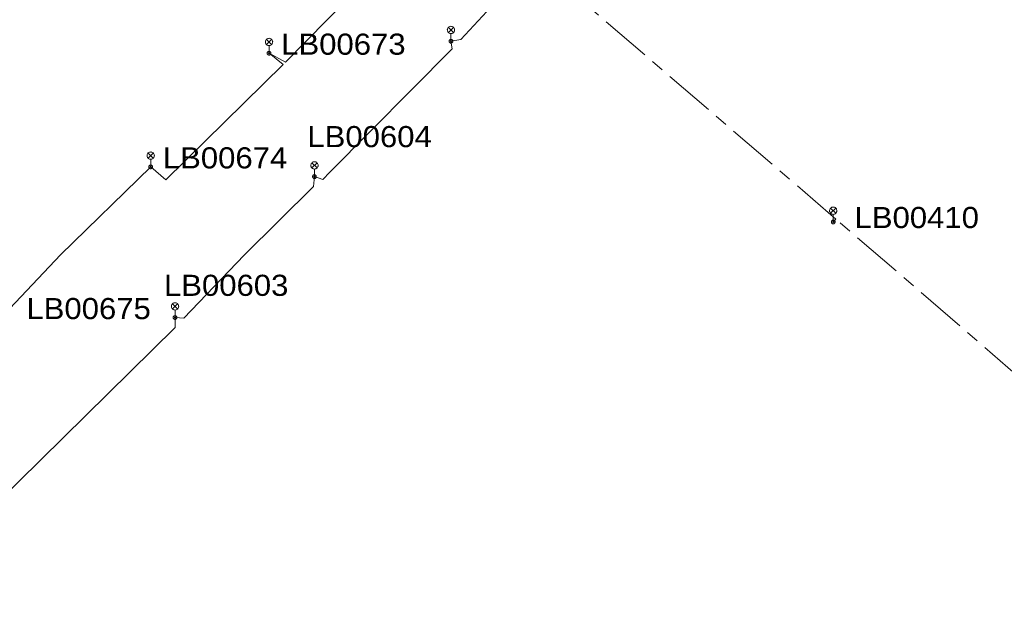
# Model space of a CAD drawing. Extents: x -688049 to -687261, y -973611 to -973038.
# Drawn here: x -687451.2 to -687350.2, y -973532.3 to -973470.9 of the extents above; entities that cross this region are included whole.
import ezdxf

# ---------------------------------------------------------------- set-up
doc = ezdxf.new("R2010")
doc.units = 0
doc.header["$LTSCALE"] = 0.87
doc.linetypes.add('LONG_DASH_SHORT_DASH', pattern=[9.9, 6, -1.2, 1.5, -1.2])
doc.layers.add('1', color=7, linetype='Continuous', lineweight=13)

msp = doc.modelspace()

# ---------------------------------------------------------------- linework, layer by layer
at = {"layer": '1', "linetype": 'LONG_DASH_SHORT_DASH'}
for p, q in [((-687367.46, -973491.32), (-687394.43, -973468.17)), ((-687367.46, -973491.32), (-687367.74, -973491.62)), ((-687341.72, -973513.53), (-687367.46, -973491.32))]:
    msp.add_line(p, q, dxfattribs=at)
at = {"layer": '1'}
for p, q in [((-687407.215, -973471.665), (-687406.685, -973472.195)), ((-687407.215, -973472.195), (-687406.685, -973471.665)), ((-687425.875, -973472.895), (-687425.345, -973473.425)), ((-687425.875, -973473.425), (-687425.345, -973472.895)), ((-687406.95, -973473.08), (-687406.95, -973472.305)), ((-687425.61, -973474.31), (-687425.61, -973473.535)), ((-687438.015, -973484.555), (-687437.485, -973485.085)), ((-687438.015, -973485.085), (-687437.485, -973484.555)), ((-687437.75, -973485.97), (-687437.75, -973485.195)), ((-687421.215, -973485.555), (-687420.685, -973486.085)), ((-687421.215, -973486.085), (-687420.685, -973485.555)), ((-687420.95, -973486.97), (-687420.95, -973486.195)), ((-687368.005, -973490.205), (-687367.475, -973490.735)), ((-687368.005, -973490.735), (-687367.475, -973490.205)), ((-687367.74, -973491.62), (-687367.74, -973490.845)), ((-687435.515, -973500.015), (-687434.985, -973500.545)), ((-687435.515, -973500.545), (-687434.985, -973500.015)), ((-687435.25, -973501.43), (-687435.25, -973500.655))]:
    msp.add_line(p, q, dxfattribs=at)
for points in [[(-687405.56, -973454.77), (-687404.641, -973456.423), (-687407.326, -973458.82), (-687411.049, -973462.143), (-687423.916, -973475.233), (-687425.61, -973474.31)], [(-687406.95, -973473.08), (-687405.926, -973472.922), (-687401.497, -973468.097), (-687399.617, -973467.227), (-687396.262, -973466.483), (-687385.16, -973458.6), (-687385.16, -973457.575), (-687384.133, -973456.25)], [(-687406.95, -973473.08), (-687406.828, -973473.853), (-687419.37, -973486.514), (-687420.101, -973487.253), (-687420.95, -973486.97)], [(-687425.61, -973474.31), (-687424.155, -973475.479), (-687436.21, -973487.29), (-687437.75, -973485.97), (-687447.006, -973494.997), (-687452.208, -973500.487), (-687452.51, -973500.51)], [(-687420.95, -973486.97), (-687421.047, -973487.985), (-687428.168, -973495.036), (-687434.342, -973501.48), (-687435.25, -973501.43)], [(-687435.25, -973501.43), (-687435.25, -973502.448), (-687465.092, -973531.834), (-687465.97, -973532.28)]]:
    msp.add_lwpolyline(points, dxfattribs=at)
for points in [[(-687406.575, -973471.93), (-687406.581, -973471.865), (-687406.598, -973471.802), (-687406.625, -973471.742), (-687406.663, -973471.689), (-687406.709, -973471.643), (-687406.763, -973471.605), (-687406.822, -973471.578), (-687406.885, -973471.561), (-687406.95, -973471.555), (-687407.015, -973471.561), (-687407.078, -973471.578), (-687407.138, -973471.605), (-687407.191, -973471.643), (-687407.237, -973471.689), (-687407.275, -973471.742), (-687407.302, -973471.802), (-687407.319, -973471.865), (-687407.325, -973471.93), (-687407.319, -973471.995), (-687407.302, -973472.058), (-687407.275, -973472.117), (-687407.237, -973472.171), (-687407.191, -973472.217), (-687407.138, -973472.255), (-687407.078, -973472.282), (-687407.015, -973472.299), (-687406.95, -973472.305), (-687406.885, -973472.299), (-687406.822, -973472.282), (-687406.763, -973472.255), (-687406.709, -973472.217), (-687406.663, -973472.171), (-687406.625, -973472.117), (-687406.598, -973472.058), (-687406.581, -973471.995)], [(-687425.235, -973473.16), (-687425.241, -973473.095), (-687425.258, -973473.032), (-687425.285, -973472.972), (-687425.323, -973472.919), (-687425.369, -973472.873), (-687425.422, -973472.835), (-687425.482, -973472.808), (-687425.545, -973472.791), (-687425.61, -973472.785), (-687425.675, -973472.791), (-687425.738, -973472.808), (-687425.798, -973472.835), (-687425.851, -973472.873), (-687425.897, -973472.919), (-687425.935, -973472.972), (-687425.962, -973473.032), (-687425.979, -973473.095), (-687425.985, -973473.16), (-687425.979, -973473.225), (-687425.962, -973473.288), (-687425.935, -973473.348), (-687425.897, -973473.401), (-687425.851, -973473.447), (-687425.798, -973473.485), (-687425.738, -973473.512), (-687425.675, -973473.529), (-687425.61, -973473.535), (-687425.545, -973473.529), (-687425.482, -973473.512), (-687425.422, -973473.485), (-687425.369, -973473.447), (-687425.323, -973473.401), (-687425.285, -973473.348), (-687425.258, -973473.288), (-687425.241, -973473.225)], [(-687406.76, -973473.08), (-687406.763, -973473.047), (-687406.771, -973473.015), (-687406.785, -973472.985), (-687406.804, -973472.958), (-687406.828, -973472.934), (-687406.855, -973472.915), (-687406.885, -973472.901), (-687406.917, -973472.893), (-687406.95, -973472.89), (-687406.983, -973472.893), (-687407.015, -973472.901), (-687407.045, -973472.915), (-687407.072, -973472.934), (-687407.096, -973472.958), (-687407.115, -973472.985), (-687407.129, -973473.015), (-687407.137, -973473.047), (-687407.14, -973473.08), (-687407.137, -973473.113), (-687407.129, -973473.145), (-687407.115, -973473.175), (-687407.096, -973473.202), (-687407.072, -973473.226), (-687407.045, -973473.245), (-687407.015, -973473.259), (-687406.983, -973473.267), (-687406.95, -973473.27), (-687406.917, -973473.267), (-687406.885, -973473.259), (-687406.855, -973473.245), (-687406.828, -973473.226), (-687406.804, -973473.202), (-687406.785, -973473.175), (-687406.771, -973473.145), (-687406.763, -973473.113)], [(-687406.9, -973473.08), (-687406.901, -973473.071), (-687406.903, -973473.063), (-687406.907, -973473.055), (-687406.912, -973473.048), (-687406.918, -973473.042), (-687406.925, -973473.037), (-687406.933, -973473.033), (-687406.941, -973473.031), (-687406.95, -973473.03), (-687406.959, -973473.031), (-687406.967, -973473.033), (-687406.975, -973473.037), (-687406.982, -973473.042), (-687406.988, -973473.048), (-687406.993, -973473.055), (-687406.997, -973473.063), (-687406.999, -973473.071), (-687407, -973473.08), (-687406.999, -973473.089), (-687406.997, -973473.097), (-687406.993, -973473.105), (-687406.988, -973473.112), (-687406.982, -973473.118), (-687406.975, -973473.123), (-687406.967, -973473.127), (-687406.959, -973473.129), (-687406.95, -973473.13), (-687406.941, -973473.129), (-687406.933, -973473.127), (-687406.925, -973473.123), (-687406.918, -973473.118), (-687406.912, -973473.112), (-687406.907, -973473.105), (-687406.903, -973473.097), (-687406.901, -973473.089)], [(-687425.42, -973474.31), (-687425.423, -973474.277), (-687425.431, -973474.245), (-687425.445, -973474.215), (-687425.464, -973474.188), (-687425.488, -973474.164), (-687425.515, -973474.145), (-687425.545, -973474.131), (-687425.577, -973474.123), (-687425.61, -973474.12), (-687425.643, -973474.123), (-687425.675, -973474.131), (-687425.705, -973474.145), (-687425.732, -973474.164), (-687425.756, -973474.188), (-687425.775, -973474.215), (-687425.789, -973474.245), (-687425.797, -973474.277), (-687425.8, -973474.31), (-687425.797, -973474.343), (-687425.789, -973474.375), (-687425.775, -973474.405), (-687425.756, -973474.432), (-687425.732, -973474.456), (-687425.705, -973474.475), (-687425.675, -973474.489), (-687425.643, -973474.497), (-687425.61, -973474.5), (-687425.577, -973474.497), (-687425.545, -973474.489), (-687425.515, -973474.475), (-687425.488, -973474.456), (-687425.464, -973474.432), (-687425.445, -973474.405), (-687425.431, -973474.375), (-687425.423, -973474.343)], [(-687425.56, -973474.31), (-687425.561, -973474.301), (-687425.563, -973474.293), (-687425.567, -973474.285), (-687425.572, -973474.278), (-687425.578, -973474.272), (-687425.585, -973474.267), (-687425.593, -973474.263), (-687425.601, -973474.261), (-687425.61, -973474.26), (-687425.619, -973474.261), (-687425.627, -973474.263), (-687425.635, -973474.267), (-687425.642, -973474.272), (-687425.648, -973474.278), (-687425.653, -973474.285), (-687425.657, -973474.293), (-687425.659, -973474.301), (-687425.66, -973474.31), (-687425.659, -973474.319), (-687425.657, -973474.327), (-687425.653, -973474.335), (-687425.648, -973474.342), (-687425.642, -973474.348), (-687425.635, -973474.353), (-687425.627, -973474.357), (-687425.619, -973474.359), (-687425.61, -973474.36), (-687425.601, -973474.359), (-687425.593, -973474.357), (-687425.585, -973474.353), (-687425.578, -973474.348), (-687425.572, -973474.342), (-687425.567, -973474.335), (-687425.563, -973474.327), (-687425.561, -973474.319)], [(-687437.375, -973484.82), (-687437.381, -973484.755), (-687437.398, -973484.692), (-687437.425, -973484.633), (-687437.463, -973484.579), (-687437.509, -973484.533), (-687437.562, -973484.495), (-687437.622, -973484.468), (-687437.685, -973484.451), (-687437.75, -973484.445), (-687437.815, -973484.451), (-687437.878, -973484.468), (-687437.938, -973484.495), (-687437.991, -973484.533), (-687438.037, -973484.579), (-687438.075, -973484.633), (-687438.102, -973484.692), (-687438.119, -973484.755), (-687438.125, -973484.82), (-687438.119, -973484.885), (-687438.102, -973484.948), (-687438.075, -973485.008), (-687438.037, -973485.061), (-687437.991, -973485.107), (-687437.938, -973485.145), (-687437.878, -973485.172), (-687437.815, -973485.189), (-687437.75, -973485.195), (-687437.685, -973485.189), (-687437.622, -973485.172), (-687437.562, -973485.145), (-687437.509, -973485.107), (-687437.463, -973485.061), (-687437.425, -973485.008), (-687437.398, -973484.948), (-687437.381, -973484.885)], [(-687437.56, -973485.97), (-687437.563, -973485.937), (-687437.571, -973485.905), (-687437.585, -973485.875), (-687437.604, -973485.848), (-687437.628, -973485.824), (-687437.655, -973485.805), (-687437.685, -973485.791), (-687437.717, -973485.783), (-687437.75, -973485.78), (-687437.783, -973485.783), (-687437.815, -973485.791), (-687437.845, -973485.805), (-687437.872, -973485.824), (-687437.896, -973485.848), (-687437.915, -973485.875), (-687437.929, -973485.905), (-687437.937, -973485.937), (-687437.94, -973485.97), (-687437.937, -973486.003), (-687437.929, -973486.035), (-687437.915, -973486.065), (-687437.896, -973486.092), (-687437.872, -973486.116), (-687437.845, -973486.135), (-687437.815, -973486.149), (-687437.783, -973486.157), (-687437.75, -973486.16), (-687437.717, -973486.157), (-687437.685, -973486.149), (-687437.655, -973486.135), (-687437.628, -973486.116), (-687437.604, -973486.092), (-687437.585, -973486.065), (-687437.571, -973486.035), (-687437.563, -973486.003)], [(-687437.7, -973485.97), (-687437.701, -973485.961), (-687437.703, -973485.953), (-687437.707, -973485.945), (-687437.712, -973485.938), (-687437.718, -973485.932), (-687437.725, -973485.927), (-687437.733, -973485.923), (-687437.741, -973485.921), (-687437.75, -973485.92), (-687437.759, -973485.921), (-687437.767, -973485.923), (-687437.775, -973485.927), (-687437.782, -973485.932), (-687437.788, -973485.938), (-687437.793, -973485.945), (-687437.797, -973485.953), (-687437.799, -973485.961), (-687437.8, -973485.97), (-687437.799, -973485.979), (-687437.797, -973485.987), (-687437.793, -973485.995), (-687437.788, -973486.002), (-687437.782, -973486.008), (-687437.775, -973486.013), (-687437.767, -973486.017), (-687437.759, -973486.019), (-687437.75, -973486.02), (-687437.741, -973486.019), (-687437.733, -973486.017), (-687437.725, -973486.013), (-687437.718, -973486.008), (-687437.712, -973486.002), (-687437.707, -973485.995), (-687437.703, -973485.987), (-687437.701, -973485.979)], [(-687420.575, -973485.82), (-687420.581, -973485.755), (-687420.598, -973485.692), (-687420.625, -973485.633), (-687420.663, -973485.579), (-687420.709, -973485.533), (-687420.763, -973485.495), (-687420.822, -973485.468), (-687420.885, -973485.451), (-687420.95, -973485.445), (-687421.015, -973485.451), (-687421.078, -973485.468), (-687421.138, -973485.495), (-687421.191, -973485.533), (-687421.237, -973485.579), (-687421.275, -973485.633), (-687421.302, -973485.692), (-687421.319, -973485.755), (-687421.325, -973485.82), (-687421.319, -973485.885), (-687421.302, -973485.948), (-687421.275, -973486.008), (-687421.237, -973486.061), (-687421.191, -973486.107), (-687421.138, -973486.145), (-687421.078, -973486.172), (-687421.015, -973486.189), (-687420.95, -973486.195), (-687420.885, -973486.189), (-687420.822, -973486.172), (-687420.763, -973486.145), (-687420.709, -973486.107), (-687420.663, -973486.061), (-687420.625, -973486.008), (-687420.598, -973485.948), (-687420.581, -973485.885)], [(-687420.76, -973486.97), (-687420.763, -973486.937), (-687420.771, -973486.905), (-687420.785, -973486.875), (-687420.804, -973486.848), (-687420.828, -973486.824), (-687420.855, -973486.805), (-687420.885, -973486.791), (-687420.917, -973486.783), (-687420.95, -973486.78), (-687420.983, -973486.783), (-687421.015, -973486.791), (-687421.045, -973486.805), (-687421.072, -973486.824), (-687421.096, -973486.848), (-687421.115, -973486.875), (-687421.129, -973486.905), (-687421.137, -973486.937), (-687421.14, -973486.97), (-687421.137, -973487.003), (-687421.129, -973487.035), (-687421.115, -973487.065), (-687421.096, -973487.092), (-687421.072, -973487.116), (-687421.045, -973487.135), (-687421.015, -973487.149), (-687420.983, -973487.157), (-687420.95, -973487.16), (-687420.917, -973487.157), (-687420.885, -973487.149), (-687420.855, -973487.135), (-687420.828, -973487.116), (-687420.804, -973487.092), (-687420.785, -973487.065), (-687420.771, -973487.035), (-687420.763, -973487.003)], [(-687420.9, -973486.97), (-687420.901, -973486.961), (-687420.903, -973486.953), (-687420.907, -973486.945), (-687420.912, -973486.938), (-687420.918, -973486.932), (-687420.925, -973486.927), (-687420.933, -973486.923), (-687420.941, -973486.921), (-687420.95, -973486.92), (-687420.959, -973486.921), (-687420.967, -973486.923), (-687420.975, -973486.927), (-687420.982, -973486.932), (-687420.988, -973486.938), (-687420.993, -973486.945), (-687420.997, -973486.953), (-687420.999, -973486.961), (-687421, -973486.97), (-687420.999, -973486.979), (-687420.997, -973486.987), (-687420.993, -973486.995), (-687420.988, -973487.002), (-687420.982, -973487.008), (-687420.975, -973487.013), (-687420.967, -973487.017), (-687420.959, -973487.019), (-687420.95, -973487.02), (-687420.941, -973487.019), (-687420.933, -973487.017), (-687420.925, -973487.013), (-687420.918, -973487.008), (-687420.912, -973487.002), (-687420.907, -973486.995), (-687420.903, -973486.987), (-687420.901, -973486.979)], [(-687367.365, -973490.47), (-687367.371, -973490.405), (-687367.388, -973490.342), (-687367.415, -973490.283), (-687367.453, -973490.229), (-687367.499, -973490.183), (-687367.552, -973490.145), (-687367.612, -973490.118), (-687367.675, -973490.101), (-687367.74, -973490.095), (-687367.805, -973490.101), (-687367.868, -973490.118), (-687367.928, -973490.145), (-687367.981, -973490.183), (-687368.027, -973490.229), (-687368.065, -973490.283), (-687368.092, -973490.342), (-687368.109, -973490.405), (-687368.115, -973490.47), (-687368.109, -973490.535), (-687368.092, -973490.598), (-687368.065, -973490.658), (-687368.027, -973490.711), (-687367.981, -973490.757), (-687367.928, -973490.795), (-687367.868, -973490.822), (-687367.805, -973490.839), (-687367.74, -973490.845), (-687367.675, -973490.839), (-687367.612, -973490.822), (-687367.552, -973490.795), (-687367.499, -973490.757), (-687367.453, -973490.711), (-687367.415, -973490.658), (-687367.388, -973490.598), (-687367.371, -973490.535)], [(-687367.55, -973491.62), (-687367.553, -973491.587), (-687367.561, -973491.555), (-687367.575, -973491.525), (-687367.594, -973491.498), (-687367.618, -973491.474), (-687367.645, -973491.455), (-687367.675, -973491.441), (-687367.707, -973491.433), (-687367.74, -973491.43), (-687367.773, -973491.433), (-687367.805, -973491.441), (-687367.835, -973491.455), (-687367.862, -973491.474), (-687367.886, -973491.498), (-687367.905, -973491.525), (-687367.919, -973491.555), (-687367.927, -973491.587), (-687367.93, -973491.62), (-687367.927, -973491.653), (-687367.919, -973491.685), (-687367.905, -973491.715), (-687367.886, -973491.742), (-687367.862, -973491.766), (-687367.835, -973491.785), (-687367.805, -973491.799), (-687367.773, -973491.807), (-687367.74, -973491.81), (-687367.707, -973491.807), (-687367.675, -973491.799), (-687367.645, -973491.785), (-687367.618, -973491.766), (-687367.594, -973491.742), (-687367.575, -973491.715), (-687367.561, -973491.685), (-687367.553, -973491.653)], [(-687367.69, -973491.62), (-687367.691, -973491.611), (-687367.693, -973491.603), (-687367.697, -973491.595), (-687367.702, -973491.588), (-687367.708, -973491.582), (-687367.715, -973491.577), (-687367.723, -973491.573), (-687367.731, -973491.571), (-687367.74, -973491.57), (-687367.749, -973491.571), (-687367.757, -973491.573), (-687367.765, -973491.577), (-687367.772, -973491.582), (-687367.778, -973491.588), (-687367.783, -973491.595), (-687367.787, -973491.603), (-687367.789, -973491.611), (-687367.79, -973491.62), (-687367.789, -973491.629), (-687367.787, -973491.637), (-687367.783, -973491.645), (-687367.778, -973491.652), (-687367.772, -973491.658), (-687367.765, -973491.663), (-687367.757, -973491.667), (-687367.749, -973491.669), (-687367.74, -973491.67), (-687367.731, -973491.669), (-687367.723, -973491.667), (-687367.715, -973491.663), (-687367.708, -973491.658), (-687367.702, -973491.652), (-687367.697, -973491.645), (-687367.693, -973491.637), (-687367.691, -973491.629)], [(-687434.875, -973500.28), (-687434.881, -973500.215), (-687434.898, -973500.152), (-687434.925, -973500.092), (-687434.963, -973500.039), (-687435.009, -973499.993), (-687435.062, -973499.955), (-687435.122, -973499.928), (-687435.185, -973499.911), (-687435.25, -973499.905), (-687435.315, -973499.911), (-687435.378, -973499.928), (-687435.438, -973499.955), (-687435.491, -973499.993), (-687435.537, -973500.039), (-687435.575, -973500.092), (-687435.602, -973500.152), (-687435.619, -973500.215), (-687435.625, -973500.28), (-687435.619, -973500.345), (-687435.602, -973500.408), (-687435.575, -973500.468), (-687435.537, -973500.521), (-687435.491, -973500.567), (-687435.438, -973500.605), (-687435.378, -973500.632), (-687435.315, -973500.649), (-687435.25, -973500.655), (-687435.185, -973500.649), (-687435.122, -973500.632), (-687435.062, -973500.605), (-687435.009, -973500.567), (-687434.963, -973500.521), (-687434.925, -973500.468), (-687434.898, -973500.408), (-687434.881, -973500.345)], [(-687435.06, -973501.43), (-687435.063, -973501.397), (-687435.071, -973501.365), (-687435.085, -973501.335), (-687435.104, -973501.308), (-687435.128, -973501.284), (-687435.155, -973501.265), (-687435.185, -973501.251), (-687435.217, -973501.243), (-687435.25, -973501.24), (-687435.283, -973501.243), (-687435.315, -973501.251), (-687435.345, -973501.265), (-687435.372, -973501.284), (-687435.396, -973501.308), (-687435.415, -973501.335), (-687435.429, -973501.365), (-687435.437, -973501.397), (-687435.44, -973501.43), (-687435.437, -973501.463), (-687435.429, -973501.495), (-687435.415, -973501.525), (-687435.396, -973501.552), (-687435.372, -973501.576), (-687435.345, -973501.595), (-687435.315, -973501.609), (-687435.283, -973501.617), (-687435.25, -973501.62), (-687435.217, -973501.617), (-687435.185, -973501.609), (-687435.155, -973501.595), (-687435.128, -973501.576), (-687435.104, -973501.552), (-687435.085, -973501.525), (-687435.071, -973501.495), (-687435.063, -973501.463)], [(-687435.2, -973501.43), (-687435.201, -973501.421), (-687435.203, -973501.413), (-687435.207, -973501.405), (-687435.212, -973501.398), (-687435.218, -973501.392), (-687435.225, -973501.387), (-687435.233, -973501.383), (-687435.241, -973501.381), (-687435.25, -973501.38), (-687435.259, -973501.381), (-687435.267, -973501.383), (-687435.275, -973501.387), (-687435.282, -973501.392), (-687435.288, -973501.398), (-687435.293, -973501.405), (-687435.297, -973501.413), (-687435.299, -973501.421), (-687435.3, -973501.43), (-687435.299, -973501.439), (-687435.297, -973501.447), (-687435.293, -973501.455), (-687435.288, -973501.462), (-687435.282, -973501.468), (-687435.275, -973501.473), (-687435.267, -973501.477), (-687435.259, -973501.479), (-687435.25, -973501.48), (-687435.241, -973501.479), (-687435.233, -973501.477), (-687435.225, -973501.473), (-687435.218, -973501.468), (-687435.212, -973501.462), (-687435.207, -973501.455), (-687435.203, -973501.447), (-687435.201, -973501.439)]]:
    msp.add_lwpolyline(points, close=True, dxfattribs=at)

# ---------------------------------------------------------------- texts
at = {"layer": '1', "width": 1.1}
for s, p in [('LB00673', (-687424.364, -973474.47)), ('LB00604', (-687421.68, -973483.951)), ('LB00674', (-687436.504, -973486.13)), ('LB00410', (-687365.554, -973492.251)), ('LB00603', (-687436.387, -973499.206)), ('LB00675', (-687450.498, -973501.59))]:
    msp.add_text(s, height=2.167, dxfattribs=at).set_placement(p)

doc.saveas('drawing.dxf')
